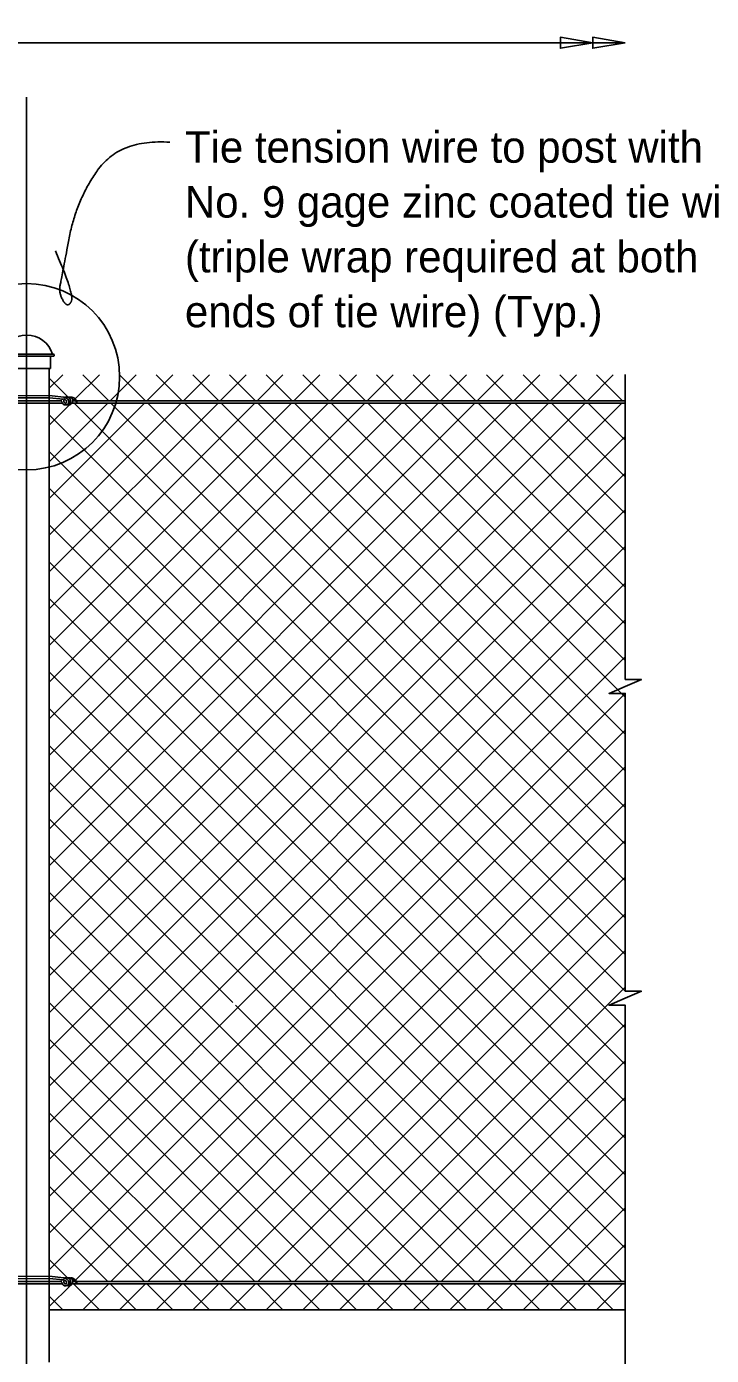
# Model space of a CAD drawing. Extents: x 0 to 41, y -96 to 25.
# Drawn here: x 24.62 to 29.01, y -79.16 to -70.63 of the extents above; entities that cross this region are included whole.
import ezdxf

# ---------------------------------------------------------------- set-up
doc = ezdxf.new("R2010")
doc.units = 0
for name, color, linetype in [('CL_Major', 7, 'Continuous'), ('Dimension', 7, 'Continuous'), ('Miscellaneous', 7, 'Continuous'), ('SteelMisc', 7, 'Continuous'), ('SteelMisc_h', 7, 'Continuous'), ('SupstrConc', 7, 'Continuous')]:
    doc.layers.add(name, color=color, linetype=linetype)

msp = doc.modelspace()

# ---------------------------------------------------------------- linework, layer by layer
at = {"layer": 'CL_Major'}
msp.add_line((24.6151, -84.4142), (24.6151, -71.0824), dxfattribs=at)
at = {"layer": 'Dimension'}
for points in [[(13.615, -70.732), (15.0787, -70.732), (15.0787, -70.6286), (15.1237, -70.732), (15.1687, -70.8353), (15.1687, -70.732), (28.4596, -70.732)], [(28.4596, -72.861), (28.4596, -74.8173), (28.5629, -74.8173), (28.4596, -74.8623), (28.3562, -74.9073), (28.4596, -74.9073), (28.4596, -75.8009)], [(28.4596, -75.8009), (28.4596, -76.8187), (28.5629, -76.8187), (28.4596, -76.8637), (28.3562, -76.9087), (28.4596, -76.9087), (28.4596, -79.113)], [(28.4596, -78.863), (28.4596, -80.7139), (28.5629, -80.7139), (28.4596, -80.7589), (28.3562, -80.8039), (28.4596, -80.8039), (28.4596, -82.3464)]]:
    msp.add_lwpolyline(points, dxfattribs=at)
for points in [[(28.2513, -70.732), (28.0431, -70.6967), (28.0431, -70.7673)], [(28.4596, -70.732), (28.2513, -70.6967), (28.2513, -70.7673)]]:
    msp.add_lwpolyline(points, close=True, dxfattribs=at)
msp.add_circle((24.615, -72.8755), 0.5976, dxfattribs=at)
msp.add_open_spline([(25.5348, -71.3706), (25.216, -71.3507), (24.9346, -71.7396), (24.8419, -72.2356), (24.8201, -72.3378), (24.8799, -72.4375), (24.9246, -72.3478), (24.8002, -72.0686)], degree=2, dxfattribs=at)
at = {"layer": 'Miscellaneous'}
for p, q in [((24.7609, -72.9497), (24.8475, -72.8631)), ((24.7609, -72.8839), (24.8832, -73.0062)), ((24.928, -73.0182), (25.0832, -72.8631)), ((24.9757, -72.8631), (25.1424, -73.0298)), ((25.1522, -73.0298), (25.3189, -72.8631)), ((25.2114, -72.8631), (25.3781, -73.0298)), ((25.3879, -73.0298), (25.5546, -72.8631)), ((25.4471, -72.8631), (25.6138, -73.0298)), ((25.6236, -73.0298), (25.7903, -72.8631)), ((25.6828, -72.8631), (25.8495, -73.0298)), ((25.8593, -73.0298), (26.026, -72.8631)), ((25.9185, -72.8631), (26.0852, -73.0298)), ((26.095, -73.0298), (26.2617, -72.8631)), ((26.1542, -72.8631), (26.3209, -73.0298)), ((26.3307, -73.0298), (26.4974, -72.8631)), ((26.3899, -72.8631), (26.5566, -73.0298)), ((26.5664, -73.0298), (26.7331, -72.8631)), ((26.6257, -72.8631), (26.7923, -73.0298)), ((26.8021, -73.0298), (26.9688, -72.8631)), ((26.8614, -72.8631), (27.028, -73.0298)), ((27.0378, -73.0298), (27.2045, -72.8631)), ((27.0971, -72.8631), (27.2637, -73.0298)), ((27.2735, -73.0298), (27.4402, -72.8631)), ((27.3328, -72.8631), (27.4994, -73.0298)), ((27.5092, -73.0298), (27.6759, -72.8631)), ((27.5685, -72.8631), (27.7351, -73.0298)), ((27.7449, -73.0298), (27.9116, -72.8631)), ((27.8042, -72.8631), (27.9708, -73.0298)), ((27.9806, -73.0298), (28.1473, -72.8631)), ((28.0399, -72.8631), (28.2065, -73.0298)), ((28.2163, -73.0298), (28.383, -72.8631)), ((28.2756, -72.8631), (28.4422, -73.0298)), ((24.7609, -76.0138), (27.7302, -73.0445)), ((24.7609, -75.5424), (27.2588, -73.0445)), ((24.7609, -75.071), (26.7874, -73.0445)), ((24.7609, -74.5996), (26.316, -73.0445)), ((24.7609, -76.4852), (28.2016, -73.0445)), ((24.7609, -74.3639), (26.0803, -73.0445)), ((24.7609, -74.8353), (26.5517, -73.0445)), ((24.7609, -75.3067), (27.0231, -73.0445)), ((24.7609, -75.7781), (27.4945, -73.0445)), ((24.7609, -76.2495), (27.9659, -73.0445)), ((24.7609, -76.7209), (28.4373, -73.0445)), ((24.7609, -74.1282), (25.8446, -73.0445)), ((24.7609, -73.6568), (25.3732, -73.0445)), ((24.7609, -73.4211), (25.1375, -73.0445)), ((24.7609, -73.1854), (24.8904, -73.0559)), ((24.7653, -73.888), (25.6089, -73.0445)), ((24.9165, -73.0298), (24.921, -73.0253)), ((24.9214, -73.0445), (28.4595, -76.5826)), ((25.1572, -73.0445), (28.4595, -76.3469)), ((25.3929, -73.0445), (28.4595, -76.1112)), ((25.6286, -73.0445), (28.4595, -75.8755)), ((25.8643, -73.0445), (28.4595, -75.6398)), ((26.1, -73.0445), (28.4595, -75.4041)), ((26.3357, -73.0445), (28.4595, -75.1684)), ((26.5714, -73.0445), (28.4595, -74.9327)), ((26.8071, -73.0445), (28.4595, -74.697)), ((27.0428, -73.0445), (28.4595, -74.4613)), ((27.2785, -73.0445), (28.4595, -74.2256)), ((27.5142, -73.0445), (28.4595, -73.9899)), ((27.7499, -73.0445), (28.4595, -73.7542)), ((27.9856, -73.0445), (28.4595, -73.5185)), ((28.2213, -73.0445), (28.4595, -73.2828)), ((24.7609, -73.1196), (28.4595, -76.8183)), ((24.7609, -76.9566), (28.4595, -73.258)), ((24.7609, -73.3554), (28.4595, -77.054)), ((24.7609, -77.1923), (28.4595, -73.4937)), ((24.7609, -73.5911), (28.4595, -77.2897)), ((24.7609, -77.428), (28.4595, -73.7294)), ((24.7609, -73.8268), (28.4595, -77.5254)), ((24.7609, -77.6637), (28.4595, -73.9651)), ((24.7609, -74.0625), (28.4595, -77.7611)), ((24.7609, -77.8994), (28.4595, -74.2008)), ((24.7609, -74.2982), (28.4595, -77.9968)), ((24.7609, -78.1351), (28.4595, -74.4365)), ((24.7609, -74.5339), (28.4595, -78.2325)), ((24.7609, -78.3708), (28.4595, -74.6722)), ((24.7609, -74.7696), (28.4595, -78.4682)), ((24.7609, -78.6065), (28.4595, -74.9079)), ((24.7609, -75.0053), (28.4373, -78.6817)), ((24.9303, -78.6728), (28.4595, -75.1436)), ((24.7609, -75.241), (28.2016, -78.6817)), ((25.1572, -78.6817), (28.4595, -75.3793)), ((24.7609, -75.4767), (27.9659, -78.6817)), ((25.3929, -78.6817), (28.4595, -75.615)), ((24.7609, -75.7124), (25.9395, -76.8909)), ((25.6286, -78.6817), (28.4595, -75.8507)), ((24.7609, -75.9481), (27.4945, -78.6817)), ((25.8643, -78.6817), (28.4595, -76.0864)), ((24.7609, -76.1838), (27.2588, -78.6817)), ((26.1, -78.6817), (28.4595, -76.3221)), ((24.7609, -76.4195), (27.0231, -78.6817)), ((26.3357, -78.6817), (28.4595, -76.5578)), ((24.7609, -76.6552), (26.7874, -78.6817)), ((26.5714, -78.6817), (28.4595, -76.7935)), ((24.7609, -76.8909), (26.5517, -78.6817)), ((25.9572, -76.9087), (27.7302, -78.6817)), ((26.8071, -78.6817), (28.4595, -77.0292)), ((24.7609, -77.1266), (26.316, -78.6817)), ((27.0428, -78.6817), (28.4595, -77.2649)), ((24.7609, -77.3623), (26.0803, -78.6817)), ((27.2785, -78.6817), (28.4595, -77.5006)), ((24.7609, -77.598), (25.8446, -78.6817)), ((27.5142, -78.6817), (28.4595, -77.7363)), ((24.7609, -77.8337), (25.6089, -78.6817)), ((27.7499, -78.6817), (28.4595, -77.972)), ((24.7609, -78.0694), (25.3732, -78.6817)), ((27.9856, -78.6817), (28.4595, -78.2077)), ((24.7609, -78.3051), (25.1375, -78.6817)), ((28.2213, -78.6817), (28.4595, -78.4434)), ((24.7609, -78.5408), (24.8783, -78.6582)), ((24.9165, -78.6964), (25.0832, -78.8631)), ((24.9757, -78.8631), (25.1424, -78.6964)), ((25.1522, -78.6964), (25.3189, -78.8631)), ((25.2114, -78.8631), (25.3781, -78.6964)), ((25.3879, -78.6964), (25.5546, -78.8631)), ((25.4471, -78.8631), (25.6138, -78.6964)), ((25.6236, -78.6964), (25.7903, -78.8631)), ((25.6828, -78.8631), (25.8495, -78.6964)), ((25.8593, -78.6964), (26.026, -78.8631)), ((25.9185, -78.8631), (26.0852, -78.6964)), ((26.095, -78.6964), (26.2617, -78.8631)), ((26.1542, -78.8631), (26.3209, -78.6964)), ((26.3307, -78.6964), (26.4974, -78.8631)), ((26.3899, -78.8631), (26.5566, -78.6964)), ((26.5664, -78.6964), (26.7331, -78.8631)), ((26.6257, -78.8631), (26.7923, -78.6964)), ((26.8021, -78.6964), (26.9688, -78.8631)), ((26.8614, -78.8631), (27.028, -78.6964)), ((27.0378, -78.6964), (27.2045, -78.8631)), ((27.0971, -78.8631), (27.2637, -78.6964)), ((27.2735, -78.6964), (27.4402, -78.8631)), ((27.3328, -78.8631), (27.4994, -78.6964)), ((27.5092, -78.6964), (27.6759, -78.8631)), ((27.5685, -78.8631), (27.7351, -78.6964)), ((27.7449, -78.6964), (27.9116, -78.8631)), ((27.8042, -78.8631), (27.9708, -78.6964)), ((27.9806, -78.6964), (28.1473, -78.8631)), ((28.0399, -78.8631), (28.2065, -78.6964)), ((28.2163, -78.6964), (28.383, -78.8631)), ((28.2756, -78.8631), (28.4422, -78.6964)), ((24.7609, -78.8422), (24.8992, -78.7039)), ((24.7641, -78.7798), (24.8475, -78.8631))]:
    msp.add_line(p, q, dxfattribs=at)
at = {"layer": 'SteelMisc'}
for p, q in [((24.4427, -72.7311), (24.7873, -72.7311)), ((24.7873, -72.7434), (24.4427, -72.7434)), ((24.7691, -72.8231), (24.7691, -72.7434)), ((24.7691, -72.8231), (24.461, -72.8231)), ((24.7609, -79.1982), (24.7609, -72.8231)), ((24.4692, -72.9972), (24.7604, -72.9955)), ((24.4692, -73.0117), (24.7604, -73.01)), ((24.7604, -72.9955), (24.8547, -73.0066)), ((24.7604, -73.01), (24.8525, -73.0194)), ((24.7609, -73.0298), (24.8413, -73.0298)), ((24.7609, -73.0445), (24.8439, -73.0445)), ((24.9067, -73.0445), (28.4595, -73.0445)), ((24.9116, -73.0298), (24.9269, -73.0298)), ((24.9353, -73.0298), (28.4595, -73.0298)), ((24.4692, -78.6491), (24.7604, -78.6474)), ((24.4692, -78.6636), (24.7604, -78.6619)), ((24.7604, -78.6474), (24.8547, -78.6585)), ((24.7604, -78.6619), (24.8525, -78.6713)), ((24.7609, -78.6817), (24.8413, -78.6817)), ((24.7609, -78.6964), (24.8439, -78.6964)), ((24.9059, -78.6964), (28.4595, -78.6964)), ((24.9116, -78.6817), (24.9269, -78.6817)), ((24.9353, -78.6817), (28.4595, -78.6817))]:
    msp.add_line(p, q, dxfattribs=at)
msp.add_arc((24.7872, -72.7374), 0.00613, 271.1647, 88.8353, dxfattribs=at)
for centre, major_axis, ratio, start_param, end_param in [((24.6157, -72.7722), (0.1711, 0), 0.957868, 0.252602, 2.888574), ((24.8661, -73.0333), (-0.0251, 0), 0.957868, 0.055352, 0.751829), ((24.8661, -73.0333), (-0.0251, 0), 0.957868, 5.673972, 5.875498), ((24.8732, -73.0212), (-0.0391, 0), 0.957868, 0.863445, 1.200597), ((24.8556, -73.0314), (0.0303, -0.0108), 0.724765, 6.241815, 8.212701), ((24.8506, -73.0443), (0.0259, 0), 0.957868, 0.655696, 1.505671), ((24.8663, -73.032), (-0.0119, 0), 0.957868, 5.149694, 6.840495), ((24.8663, -73.032), (-0.0119, 0), 0.957868, 0.560069, 0.643501), ((24.8646, -73.0378), (0.00795, 0), 0.957868, 3.252108, 6.425997), ((24.8658, -73.04), (-0.0206, -0.0021), 0.798607, 1.063032, 2.950031), ((24.8691, -73.0332), (-0.0295, 0), 0.957868, 2.243629, 5.062245), ((24.859, -73.0354), (0.0139, 0), 0.957868, 5.660958, 7.342751), ((24.8792, -73.04), (-0.0206, -0.0021), 0.798607, 1.063032, 1.956656), ((24.8879, -73.0278), (-0.023, 0), 0.957868, 3.312645, 4.992926), ((24.8853, -73.0343), (-0.0231, 0), 0.957868, 1.403365, 2.503632), ((24.9004, -73.0422), (-0.0373, 0), 0.957868, 3.175144, 4.79635), ((24.8867, -73.0303), (0.0249, 0), 0.957868, 5.476514, 6.557353), ((24.8792, -73.0819), (0.0724, 0), 0.957868, 0.631079, 1.121037), ((24.8661, -78.6852), (-0.0251, 0), 0.957868, 0.055352, 0.751829), ((24.8661, -78.6852), (-0.0251, 0), 0.957868, 5.673972, 5.875498), ((24.8732, -78.6731), (-0.0391, 0), 0.957868, 0.863445, 1.200597), ((24.8556, -78.6833), (0.0303, -0.0108), 0.724765, 6.241815, 8.212701), ((24.8506, -78.6962), (0.0259, 0), 0.957868, 0.655696, 1.505671), ((24.8663, -78.6839), (-0.0119, 0), 0.957868, 5.149694, 6.840495), ((24.8663, -78.6839), (-0.0119, 0), 0.957868, 0.560069, 0.643501), ((24.8646, -78.6897), (0.00795, 0), 0.957868, 3.252108, 6.425997), ((24.8658, -78.6919), (-0.0206, -0.0021), 0.798607, 1.063032, 2.950031), ((24.8691, -78.6851), (-0.0295, 0), 0.957868, 2.243629, 5.062245), ((24.859, -78.6874), (0.0139, 0), 0.957868, 5.660958, 7.342751), ((24.8879, -78.6797), (-0.023, 0), 0.957868, 3.312645, 4.992926), ((24.8853, -78.6862), (-0.0231, 0), 0.957868, 1.403365, 2.503632), ((24.9004, -78.6942), (-0.0373, 0), 0.957868, 3.175144, 4.79635), ((24.8867, -78.6822), (0.0249, 0), 0.957868, 5.476514, 6.557353), ((24.8792, -78.7339), (0.0724, 0), 0.957868, 0.631079, 1.121037), ((24.8792, -78.6919), (-0.0206, -0.0021), 0.798607, 1.063032, 1.956656)]:
    msp.add_ellipse(centre, major_axis=major_axis, ratio=ratio, start_param=start_param, end_param=end_param, dxfattribs=at)
at = {"layer": 'SteelMisc_h'}
for p, q in [((24.4692, -73.0298), (24.7609, -73.0298)), ((24.4692, -73.0445), (24.7609, -73.0445)), ((24.4692, -78.6817), (24.7609, -78.6817)), ((24.4692, -78.6964), (24.7609, -78.6964))]:
    msp.add_line(p, q, dxfattribs=at)
at = {"layer": 'SupstrConc'}
for q in [(28.4595, -78.8631), (26.002, -78.8631)]:
    msp.add_line((24.7609, -78.8631), q, dxfattribs=at)

# ---------------------------------------------------------------- texts
at = {"layer": 'Dimension'}
for s, p in [('Tie tension wire to post with ', (25.632, -71.5023)), ('No. 9 gage zinc coated tie wire ', (25.632, -71.8543)), ('(triple wrap required at both ', (25.632, -72.2063)), ('ends of tie wire) (Typ.)', (25.632, -72.5583))]:
    msp.add_text(s, height=0.2016, dxfattribs=at).set_placement(p)

doc.saveas('drawing.dxf')
